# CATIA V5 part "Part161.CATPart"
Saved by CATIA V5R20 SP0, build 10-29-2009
Part number: DFA 105700-1
Revision: ANY
Definition: UNKNOWN
Nomenclature: DFA 105700-1
Source: Unknown
Bounding box of the stored display mesh (mm): x -2.853 to 2.853, y 0.2 to 2.5, z -3 to 3
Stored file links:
  C:\Users\Utente\Desktop\IO LAVORO\3D X SITO CF\CUMSA\3D files FA\FA 105712-21\Part161.CATPart
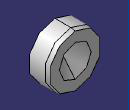
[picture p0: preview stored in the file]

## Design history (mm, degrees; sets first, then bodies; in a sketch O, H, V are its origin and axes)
Body1 "Cortar-Extruir1" (main body)
  Solid1: solid without history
